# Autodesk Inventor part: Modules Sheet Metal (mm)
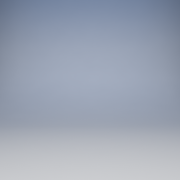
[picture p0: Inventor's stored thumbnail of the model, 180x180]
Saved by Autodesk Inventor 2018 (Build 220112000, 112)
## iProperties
Created: 2016-06
Part Number: Modules Sheet Metal (mm)
Material: Generic
Document SubType Name: Sheet Metal
Designer: Wally
Density: 1 g/cm^3
Sheet Metal Rule: Default
Appearance: Default
Author: Wally
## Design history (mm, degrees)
node "Sketch1"
other parameters: "Thickness" = 0.5, "BendRadius" = 0.5 (= Thickness), "BendReliefWidth" = 0.5 (= Thickness), "BendReliefDepth" = 0.25 (= 0.5 x Thickness), "CornerReliefSize" = 2 (= 4 x Thickness), "SeamGap" = 0.01, "MinimumRemnant" = 1 (= 2 x Thickness), "TransitionRadius" = 0.5 (= BendRadius), "JacobiRadiusSize" = 0.5 (= BendRadius), "GapSize" = 0.5 (= Thickness)
